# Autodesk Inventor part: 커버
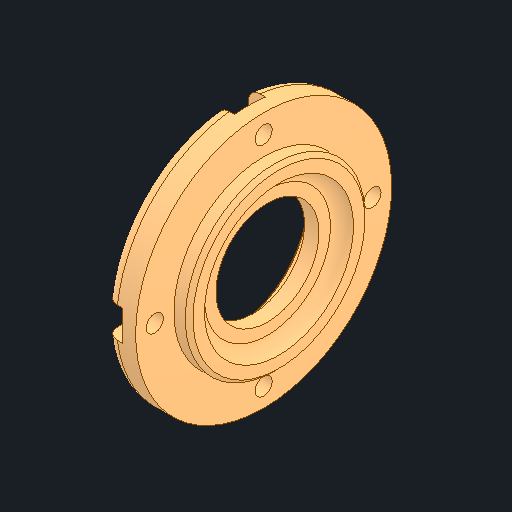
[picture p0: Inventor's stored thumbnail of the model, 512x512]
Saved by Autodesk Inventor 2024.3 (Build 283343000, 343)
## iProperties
Created: 2025-07
Part Number: 커버
Material: 알루미늄 6061
Document SubType Name: Modeling
Designer: user
Density: 2.7 g/cm^3
Appearance: 기본값
Author: jhkim
Sending System: Autodesk Inventor 2026
Preprocessor: ST-DEVELOPER v20.1
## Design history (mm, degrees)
feature "솔리드1"
node "솔리드2"
